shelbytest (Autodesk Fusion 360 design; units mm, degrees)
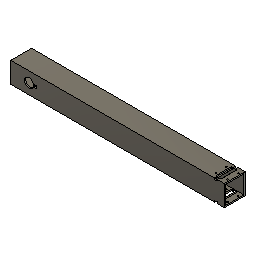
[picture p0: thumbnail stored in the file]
parameter "d495" = 0
parameter "d496" = 0
parameter "d497" = 0
parameter "d498" = 0
sketch "Sketch1" plane through (0, 0, 0) normal (1, 0, 0) x axis (0, 0, -1)
  line L1 (50.8, 0) -> (0, 0)
  line L2 (50.8, 50.8) -> (50.8, 0)
  line L3 (0, 50.8) -> (50.8, 50.8)
  line L4 (0, 0) -> (0, 50.8)
  line L5 (47.5234, 3.2766) -> (3.2766, 3.2766)
  line L6 (47.5234, 47.5234) -> (47.5234, 3.2766)
  line L7 (3.2766, 47.5234) -> (47.5234, 47.5234)
  line L8 (3.2766, 3.2766) -> (3.2766, 47.5234)
  point P1 (0, 0)
  point P2 (0, 0)
  point P3 (50.8, 0)
  point P5 (0, 50.8)
  horizontal L1
  vertical L2
  horizontal L3
  vertical L4
  coincident P1 P2
  dimension "d1_1" distance P2 P3 = 50.8
  dimension "d2_1" distance P2 P5 = 50.8
  dimension "d3_1" = -3.2766
  dimension "d158" OffsetX = 0
  dimension "d159" OffsetY = 0
  dimension "d160" OffsetZ = 0
  dimension "d161" AngleZ = 0
  dimension "d215" OffsetX = 0
  dimension "d216" OffsetY = 0
  dimension "d217" OffsetZ = 0
  dimension "d218" AngleZ = 0
  dimension "d223" OffsetX = 0
  dimension "d224" OffsetY = 0
  dimension "d225" OffsetZ = 0
  dimension "d226" AngleZ = 0
  dimension "d231" OffsetX = 0
  dimension "d232" OffsetY = 0
  dimension "d233" OffsetZ = 0
  dimension "d234" AngleZ = 0
  dimension "d239" OffsetX = 0
  dimension "d240" OffsetY = 0
  dimension "d241" OffsetZ = 0
  dimension "d242" AngleZ = 0
  dimension "d339" OffsetX = 0
  dimension "d340" OffsetY = 0
  dimension "d341" OffsetZ = 0
  dimension "d342" AngleZ = 0
  dimension "d347" OffsetX = 0
  dimension "d348" OffsetY = 0
  dimension "d349" OffsetZ = 0
  dimension "d350" AngleZ = 0
  dimension "d355" OffsetX = 0
  dimension "d356" OffsetY = 0
  dimension "d357" OffsetZ = 0
  dimension "d358" AngleZ = 0
  dimension "d363" OffsetX = 0
  dimension "d364" OffsetY = 0
  dimension "d365" OffsetZ = 0
  dimension "d366" AngleZ = 0
  dimension "d376" OffsetX = 0
  dimension "d377" OffsetY = 0
  dimension "d378" OffsetZ = 0
  dimension "d379" AngleZ = 0
  dimension "d384" OffsetX = 0
  dimension "d385" OffsetY = 0
  dimension "d386" OffsetZ = 0
  dimension "d387" AngleZ = 0
  dimension "d392" OffsetX = 0
  dimension "d393" OffsetY = 0
  dimension "d394" OffsetZ = 0
  dimension "d395" AngleZ = 0
  dimension "d479" OffsetX = 0
  dimension "d480" OffsetY = 0
  dimension "d481" OffsetZ = 0
  dimension "d482" AngleZ = 0
  dimension "d487" OffsetX = 0
  dimension "d488" OffsetY = 0
  dimension "d489" OffsetZ = 0
  dimension "d490" AngleZ = 0
extrude "Extrude1" new body sketch "Sketch1" along a picked direction blind 520.7 named "d4_1"
hole "Hole2" HoleDepth 101.6 HoleDiameter 22.225 TipAngle 118 RefDim1 44.45 (= "1 in + ( 3 / 4 ) * 1 in") RefDim2 25.4
sketch "Sketch2" plane through (0, 0, 0) normal (0, 0, 1) x axis (1, 0, 0)
  line L1 (0, 50.8) -> (520.7, 50.8)
  line L2 (0, 0) -> (0, 50.8)
  line L3 (520.7, 0) -> (0, 0)
  line L4 (496.7478, 47.498) -> (503.3518, 47.498)
  line L5 (496.7478, 54.102) -> (496.7478, 47.498)
  line L6 (503.3518, 54.102) -> (496.7478, 54.102)
  line L7 (503.3518, 47.498) -> (503.3518, 54.102)
  line L8 (496.7478, 54.102) -> (503.3518, 47.498)
  line L9 (503.3518, 54.102) -> (496.7478, 47.498)
  line L10 (496.7478, 3.302) -> (503.3518, 3.302)
  line L11 (496.7478, -3.302) -> (496.7478, 3.302)
  line L12 (503.3518, -3.302) -> (496.7478, -3.302)
  line L13 (503.3518, 3.302) -> (503.3518, -3.302)
  line L14 (496.7478, -3.302) -> (503.3518, 3.302)
  line L15 (503.3518, -3.302) -> (496.7478, 3.302)
  line L16 (520.7, 50.8) -> (520.7, 0)
  line L17 (520.7, 50.8) -> (520.7, 0)
  circle C1 centre (44.45, 25.4) radius 11.1125
  circle C2 centre (500.0498, 50.8) radius 3.302
  circle C3 centre (500.0498, 0) radius 3.302
  point P7 (500.0498, 50.8)
  point P8 (500.0498, 0)
  point P13 (500.0498, 50.8)
  point P18 (500.0498, 0)
  point P10 (496.7478, 47.498)
  point P11 (496.7478, 54.102)
  point P12 (503.3518, 54.102)
  point P16 (496.7478, -3.302)
  point P17 (503.3518, -3.302)
  point P15 (496.7478, 3.302)
  coincident L1 P7
  coincident L3 P8
  perpendicular L4 L5
  parallel L4 L6
  parallel L5 L7
  horizontal L4
  coincident L8 P13
  coincident L9 P13
  coincident P7 P13
  perpendicular L10 L11
  parallel L10 L12
  parallel L11 L13
  horizontal L10
  coincident L14 P18
  coincident L15 P18
  coincident P8 P18
  dimension "d412" diameter C2 = 6.604
  dimension "d413" diameter C3 = 6.604
  dimension "d428" distance P10 P11 = 6.604
  dimension "d429" distance P11 P12 = 6.604
  dimension "d430" distance P16 P17 = 6.604
  dimension "d431" distance P15 P16 = 6.604
  dimension "d540" distance L13 L17 = 17.3482
  dimension "d541" distance L7 L17 = 17.3482
extrude "Extrude3" cut sketch "Sketch2" profile of L1 L3 C2 C3 L4 L5 L7 L10 L11 L13 along a picked direction blind -50.8
sketch "Sketch3" plane through (0, 0, 0) normal (0, -1, 0) x axis (1, 0, 0)
  line L1 (520.7, -50.8) -> (503.3518, -50.8)
  line L2 (503.3518, 0) -> (520.7, 0)
  line L3 (493.1918, -6.35) -> (506.9078, -6.35)
  line L4 (493.1918, -19.05) -> (493.1918, -6.35)
  line L5 (506.9078, -19.05) -> (493.1918, -19.05)
  line L6 (506.9078, -6.35) -> (506.9078, -19.05)
  line L7 (493.1918, -19.05) -> (506.9078, -19.05)
  line L8 (493.1918, -44.45) -> (493.1918, -19.05)
  line L9 (506.9078, -44.45) -> (493.1918, -44.45)
  line L10 (506.9078, -19.05) -> (506.9078, -44.45)
  line L11 (503.3518, -50.8) -> (503.3518, 0)
  line L12 (496.7478, 0) -> (496.7478, -50.8)
  line L13 (520.7, 0) -> (520.7, -50.8)
  line L14 (496.7478, 0) -> (496.7478, -50.8)
  line L15 (0, 0) -> (496.7478, 0)
  line L16 (0, -50.8) -> (0, 0)
  line L17 (496.7478, -50.8) -> (0, -50.8)
  point P6 (506.9078, -6.35)
  point P9 (506.9078, -19.05)
  point P7 (493.1918, -6.35)
  point P10 (506.9078, -19.05)
  point P11 (493.1918, -19.05)
  point P13 (506.9078, -44.45)
  horizontal L3
  vertical L4
  horizontal L5
  vertical L6
  horizontal L7
  vertical L8
  horizontal L9
  vertical L10
  dimension "d418" distance P6 P9 = 12.7
  dimension "d419" distance P6 P7 = 13.716
  dimension "d420" distance P10 P11 = 13.716
  dimension "d421" distance P10 P13 = 25.4
  dimension "d422" distance L1 L9 = 6.35
  dimension "d423" distance L2 L3 = 6.35
  dimension "d432" distance L4 L12 = 3.556
  dimension "d433" distance L8 L12 = 3.556
extrude "Extrude4" cut sketch "Sketch3" profile of L3 L4 L5 L6 L7 L8 L9 L10 L11 L12 against normal blind 3.175
extrude "Extrude5" sketch "Sketch3" profile of L3 L4 L5 L6 L7 L8 L9 L10 L11 L12 blind 3.175
fillet "Fillet1" radius 1.5875 1.5875
sketch "Sketch4" plane through (0, 50.8, 0) normal (0, 1, 0) x axis (-1, 0, 0)
  line L1 (-469.3793, -6.35) -> (-469.7603, -6.35)
  line L2 (-467.7918, -42.8625) -> (-467.7918, -7.9375)
  line L3 (-469.7603, -44.45) -> (-469.3793, -44.45)
  line L4 (-471.3478, -50.8) -> (-471.3478, -46.0375)
  line L5 (0, -50.8) -> (-471.3478, -50.8)
  line L6 (0, 0) -> (0, -50.8)
  line L7 (-471.3478, 0) -> (0, 0)
  line L8 (-471.3478, -4.7625) -> (-471.3478, 0)
  line L9 (-520.7, -50.8) -> (-477.9518, -50.8)
  line L10 (-503.3518, 0) -> (-503.3518, -4.7625)
  line L11 (-520.7, 0) -> (-503.3518, 0)
  line L12 (-520.7, -50.8) -> (-520.7, 0)
  line L13 (-503.3518, -50.8) -> (-520.7, -50.8)
  line L14 (-503.3518, -46.0375) -> (-503.3518, -50.8)
  line L15 (-505.3203, -44.45) -> (-504.9393, -44.45)
  line L16 (-506.9078, -7.9375) -> (-506.9078, -42.8625)
  line L17 (-504.9393, -6.35) -> (-505.3203, -6.35)
  arc A1 centre (-469.7603, -4.7625) radius 1.5875 clockwise from (-469.7603, -6.35) to (-471.3478, -4.7625)
  arc A2 centre (-469.3793, -7.9375) radius 1.5875 clockwise from (-469.3793, -6.35) to (-467.7918, -7.9375)
  arc A3 centre (-469.7603, -46.0375) radius 1.5875 clockwise from (-471.3478, -46.0375) to (-469.7603, -44.45)
  circle C1 centre (-515.9248, -38.1) radius 2.5527
  circle C2 centre (-487.3498, -38.1) radius 2.5527
  circle C3 centre (-515.9248, -12.7) radius 2.5527
  circle C4 centre (-487.3498, -12.7) radius 2.5527
  arc A4 centre (-469.3793, -42.8625) radius 1.5875 clockwise from (-467.7918, -42.8625) to (-469.3793, -44.45)
  arc A5 centre (-504.9393, -4.7625) radius 1.5875 clockwise from (-503.3518, -4.7625) to (-504.9393, -6.35)
  arc A6 centre (-504.9393, -46.0375) radius 1.5875 clockwise from (-504.9393, -44.45) to (-503.3518, -46.0375)
  arc A7 centre (-505.3203, -42.8625) radius 1.5875 clockwise from (-505.3203, -44.45) to (-506.9078, -42.8625)
  arc A8 centre (-505.3203, -7.9375) radius 1.5875 clockwise from (-506.9078, -7.9375) to (-505.3203, -6.35)
  point P17 (-515.9248, -38.1)
  dimension "d441" diameter C1 = 5.1054
  dimension "d443" distance P17 L9 = 12.7
  dimension "d539" distance P17 L12 = 4.7752
  dimension "d446" R-Pattern1-uDistance = 28.575
  dimension "d447" R-Pattern1-vDistance = 25.4
hole "Hole3" HoleDepth 50.8 HoleDiameter 3.429 TipAngle 118
sketch "Sketch5" plane through (0, 0, 0) normal (0, 0, 1) x axis (1, 0, 0)
  line L1 (503.3518, 47.498) -> (503.3518, 50.8)
  line L2 (496.7478, 47.498) -> (503.3518, 47.498)
  line L3 (496.7478, 50.8) -> (496.7478, 47.498)
  line L4 (0, 50.8) -> (496.7478, 50.8)
  line L5 (0, 0) -> (0, 50.8)
  line L6 (496.7478, 0) -> (0, 0)
  line L7 (496.7478, 3.302) -> (496.7478, 0)
  line L8 (503.3518, 3.302) -> (496.7478, 3.302)
  line L9 (503.3518, 0) -> (503.3518, 3.302)
  line L10 (520.7, 0) -> (503.3518, 0)
  line L11 (520.7, 50.8) -> (520.7, 0)
  line L12 (503.3518, 50.8) -> (520.7, 50.8)
  circle C1 centre (44.45, 25.4) radius 11.1125
  circle C2 centre (60.325, 25.4) radius 3.3782
  point P14 (44.45, 25.4)
  point P15 (60.325, 25.4)
  dimension "d542" diameter C2 = 6.7564
  dimension "d543" distance P14 P15 = 15.875
  dimension "d544" distance L4 P15 = 25.4
hole "Hole4" HoleDepth 38.1 HoleDiameter 6.7564 TipAngle 118
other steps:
thread "Thread1"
